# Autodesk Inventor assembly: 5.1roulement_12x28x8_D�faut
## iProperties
Created: 2011-01
Part Number: 5.1roulement_12x28x8_D�faut
Document SubType Name: Assembly
Designer: eric
Mass: 2.73783 g
Surface Area: 33.63 cm^2
Volume: 2.73783 cm^3
Density: 1 g/cm^3
Author: eric
